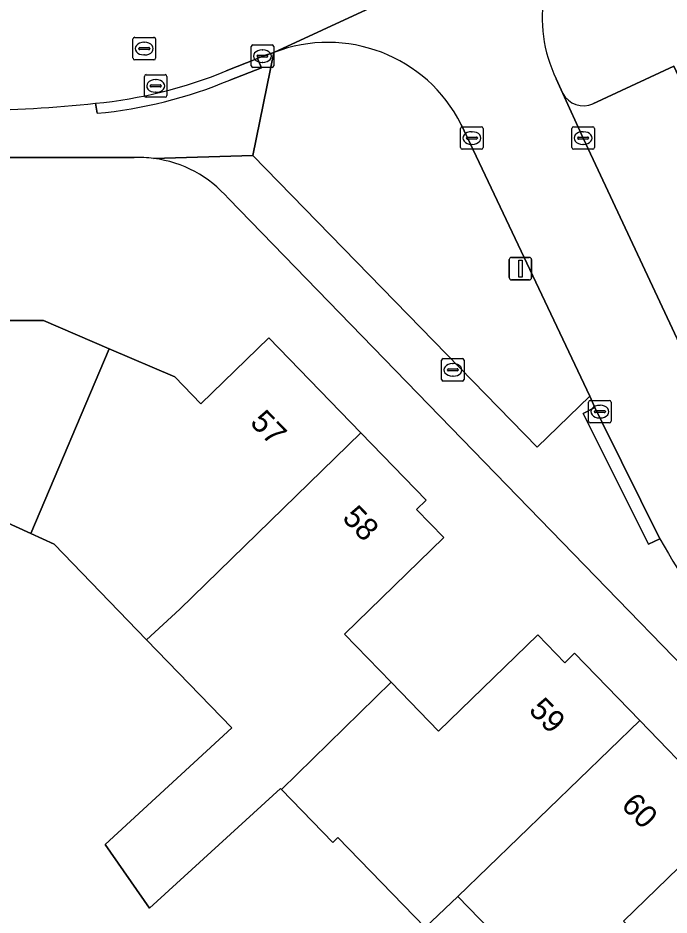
# Model space of a CAD drawing. Extents: x 162879 to 165540, y 384011 to 385181.
# Drawn here: x 163852.88 to 163881.82, y 384275.54 to 384315.4 of the extents above; entities that cross this region are included whole.
import ezdxf

# ---------------------------------------------------------------- set-up
doc = ezdxf.new("R2010")
doc.units = 0
for name, color, linetype in [('IMGEO_Erf', 7, 'Continuous'), ('IMGEO_Groenvoorziening', 7, 'Continuous'), ('IMGEO_Kolk', 7, 'Continuous'), ('IMGEO_Lichtmast', 7, 'Continuous'), ('IMGEO_Pand', 7, 'Continuous'), ('IMGEO_Pand_nummerreeks', 7, 'Continuous'), ('IMGEO_Parkeervlak_open', 7, 'Continuous'), ('IMGEO_Rijbaan_lokaal_gesloten', 7, 'Continuous'), ('IMGEO_Rioolput', 7, 'Continuous'), ('IMGEO_Voetpad_open', 7, 'Continuous')]:
    doc.layers.add(name, color=color, linetype=linetype)

msp = doc.modelspace()

# ---------------------------------------------------------------- linework, layer by layer
at = {"layer": 'IMGEO_Erf'}
for points in [[(163858.049, 384309.199), (163850.754, 384309.197)], [(163899.33, 384269.205), (163862.239, 384307.377)], [(163852.36, 384301.956), (163854.02, 384301.957), (163856.929, 384300.707), (163859.847, 384299.453), (163861.001, 384298.26), (163864.034, 384301.194), (163868.122, 384296.969), (163871.022, 384293.972), (163870.6, 384293.562), (163871.811, 384292.314), (163867.394, 384288.028), (163869.463, 384285.896), (163871.58, 384283.715), (163875.993, 384287.998), (163877.197, 384286.756), (163877.627, 384287.173), (163880.526, 384284.185), (163883.421, 384281.202), (163882.999, 384280.792), (163884.207, 384279.548), (163879.797, 384275.268)], [(163884.706, 384263.725), (163880.945, 384267.599), (163879.273, 384265.976), (163876.963, 384268.356), (163874.635, 384270.755), (163876.307, 384272.378), (163872.435, 384276.367), (163870.985, 384274.989), (163867.105, 384278.986), (163866.875, 384278.763), (163864.591, 384281.119), (163864.549, 384281.163), (163858.731, 384275.845), (163856.749, 384278.678), (163862.387, 384283.859), (163858.599, 384287.774), (163854.483, 384292.029), (163853.45, 384292.496), (163852.088, 384293.112)]]:
    msp.add_lwpolyline(points, dxfattribs=at)
for centre, radius, start, end in [((163858.24, 384303.908), 5.294, 82.74, 92.067), ((163858.245, 384303.919), 5.283, 40.8873, 82.7804)]:
    msp.add_arc(centre, radius, start, end, dxfattribs=at)
at = {"layer": 'IMGEO_Groenvoorziening'}
msp.add_lwpolyline([(163864.258, 384313.87), (163863.321, 384309.287), (163875.964, 384296.339), (163878.295, 384298.593), (163872.582, 384310.677)], dxfattribs=at)
msp.add_arc((163866.657, 384307.676), 6.642, 26.8577, 111.1697, dxfattribs=at)
at = {"layer": 'IMGEO_Kolk'}
for p, q in [((163863.321, 384314.206), (163864.173, 384314.206)), ((163863.246, 384313.28), (163863.246, 384314.132)), ((163863.734, 384313.986), (163863.759, 384313.986)), ((163864.247, 384314.132), (163864.247, 384313.28)), ((163863.505, 384313.7), (163863.505, 384313.712)), ((163863.943, 384313.663), (163863.545, 384313.663)), ((163863.548, 384313.749), (163863.946, 384313.749)), ((163863.757, 384313.426), (163863.732, 384313.426)), ((163863.989, 384313.712), (163863.989, 384313.7)), ((163864.173, 384313.206), (163863.321, 384313.206)), ((163872.558, 384309.641), (163872.558, 384310.493)), ((163872.633, 384310.567), (163873.485, 384310.567)), ((163873.046, 384310.347), (163873.071, 384310.347)), ((163873.559, 384310.493), (163873.559, 384309.641)), ((163877.502, 384309.641), (163877.502, 384310.493)), ((163877.577, 384310.567), (163878.429, 384310.567)), ((163877.99, 384310.347), (163878.015, 384310.347)), ((163878.503, 384310.493), (163878.503, 384309.641)), ((163872.817, 384310.061), (163872.817, 384310.073)), ((163873.255, 384310.024), (163872.857, 384310.024)), ((163872.86, 384310.11), (163873.258, 384310.11)), ((163873.301, 384310.073), (163873.301, 384310.061)), ((163877.761, 384310.061), (163877.761, 384310.073)), ((163878.199, 384310.024), (163877.801, 384310.024)), ((163877.804, 384310.11), (163878.202, 384310.11)), ((163878.245, 384310.073), (163878.245, 384310.061)), ((163873.485, 384309.567), (163872.633, 384309.567)), ((163873.069, 384309.787), (163873.044, 384309.787)), ((163878.429, 384309.567), (163877.577, 384309.567)), ((163878.013, 384309.787), (163877.988, 384309.787)), ((163871.786, 384300.267), (163872.638, 384300.267)), ((163871.711, 384299.341), (163871.711, 384300.193)), ((163872.199, 384300.047), (163872.224, 384300.047)), ((163872.712, 384300.193), (163872.712, 384299.341)), ((163871.97, 384299.761), (163871.97, 384299.773)), ((163872.408, 384299.724), (163872.01, 384299.724)), ((163872.013, 384299.81), (163872.411, 384299.81)), ((163872.222, 384299.487), (163872.197, 384299.487)), ((163872.454, 384299.773), (163872.454, 384299.761)), ((163872.638, 384299.267), (163871.786, 384299.267)), ((163878.248, 384297.486), (163878.248, 384298.338)), ((163878.323, 384298.412), (163879.175, 384298.412)), ((163879.249, 384298.338), (163879.249, 384297.486)), ((163878.507, 384297.906), (163878.507, 384297.918)), ((163878.945, 384297.869), (163878.547, 384297.869)), ((163878.55, 384297.955), (163878.948, 384297.955)), ((163878.736, 384298.192), (163878.761, 384298.192)), ((163878.991, 384297.918), (163878.991, 384297.906)), ((163878.759, 384297.632), (163878.734, 384297.632)), ((163879.175, 384297.412), (163878.323, 384297.412))]:
    msp.add_line(p, q, dxfattribs=at)
for points in [[(163863.321, 384314.206), (163864.173, 384314.206)], [(163863.246, 384313.28), (163863.246, 384314.132)], [(163864.247, 384314.132), (163864.247, 384313.28)], [(163864.173, 384313.206), (163863.321, 384313.206)], [(163872.558, 384309.641), (163872.558, 384310.493)], [(163872.633, 384310.567), (163873.485, 384310.567)], [(163873.559, 384310.493), (163873.559, 384309.641)], [(163877.502, 384309.641), (163877.502, 384310.493)], [(163877.577, 384310.567), (163878.429, 384310.567)], [(163878.503, 384310.493), (163878.503, 384309.641)], [(163873.485, 384309.567), (163872.633, 384309.567)], [(163878.429, 384309.567), (163877.577, 384309.567)], [(163871.786, 384300.267), (163872.638, 384300.267)], [(163871.711, 384299.341), (163871.711, 384300.193)], [(163872.712, 384300.193), (163872.712, 384299.341)], [(163872.638, 384299.267), (163871.786, 384299.267)], [(163878.248, 384297.486), (163878.248, 384298.338)], [(163878.323, 384298.412), (163879.175, 384298.412)], [(163879.249, 384298.338), (163879.249, 384297.486)], [(163879.175, 384297.412), (163878.323, 384297.412)]]:
    msp.add_lwpolyline(points, dxfattribs=at)
for centre, radius, start, end in [((163863.323, 384314.13), 0.0765, 91.552, 178.448), ((163863.323, 384314.13), 0.0765, 91.552, 178.448), ((163864.171, 384314.13), 0.0765, 1.552, 88.448), ((163864.171, 384314.13), 0.0765, 1.552, 88.448), ((163863.545, 384313.709), 0.0403, 85.8775, 175.7526), ((163863.542, 384313.699), 0.0366, 178.938, 274.7102), ((163863.946, 384313.706), 0.043, 264.8664, 352.4533), ((163863.95, 384313.711), 0.0386, 1.7309, 96.639), ((163863.323, 384313.282), 0.0765, 181.552, 268.448), ((163863.323, 384313.282), 0.0765, 181.552, 268.448), ((163864.171, 384313.282), 0.0765, 271.552, 358.448), ((163864.171, 384313.282), 0.0765, 271.552, 358.448), ((163872.635, 384310.491), 0.0765, 91.552, 178.448), ((163872.635, 384310.491), 0.0765, 91.552, 178.448), ((163873.483, 384310.491), 0.0765, 1.552, 88.448), ((163873.483, 384310.491), 0.0765, 1.552, 88.448), ((163877.579, 384310.491), 0.0765, 91.552, 178.448), ((163877.579, 384310.491), 0.0765, 91.552, 178.448), ((163878.427, 384310.491), 0.0765, 1.552, 88.448), ((163878.427, 384310.491), 0.0765, 1.552, 88.448), ((163872.857, 384310.07), 0.0403, 85.8775, 175.7526), ((163872.854, 384310.06), 0.0366, 178.938, 274.7102), ((163873.258, 384310.067), 0.043, 264.8664, 352.4533), ((163873.262, 384310.072), 0.0386, 1.7309, 96.639), ((163877.801, 384310.07), 0.0403, 85.8775, 175.7526), ((163877.798, 384310.06), 0.0366, 178.938, 274.7102), ((163878.202, 384310.067), 0.043, 264.8664, 352.4533), ((163878.206, 384310.072), 0.0386, 1.7309, 96.639), ((163872.635, 384309.643), 0.0765, 181.552, 268.448), ((163872.635, 384309.643), 0.0765, 181.552, 268.448), ((163873.483, 384309.643), 0.0765, 271.552, 358.448), ((163873.483, 384309.643), 0.0765, 271.552, 358.448), ((163877.579, 384309.643), 0.0765, 181.552, 268.448), ((163877.579, 384309.643), 0.0765, 181.552, 268.448), ((163878.427, 384309.643), 0.0765, 271.552, 358.448), ((163878.427, 384309.643), 0.0765, 271.552, 358.448), ((163871.788, 384300.191), 0.0765, 91.552, 178.448), ((163871.788, 384300.191), 0.0765, 91.552, 178.448), ((163872.636, 384300.191), 0.0765, 1.552, 88.448), ((163872.636, 384300.191), 0.0765, 1.552, 88.448), ((163872.01, 384299.77), 0.0403, 85.8775, 175.7526), ((163872.007, 384299.76), 0.0366, 178.938, 274.7102), ((163872.411, 384299.767), 0.043, 264.8664, 352.4533), ((163872.415, 384299.772), 0.0386, 1.7309, 96.639), ((163871.788, 384299.343), 0.0765, 181.552, 268.448), ((163871.788, 384299.343), 0.0765, 181.552, 268.448), ((163872.636, 384299.343), 0.0765, 271.552, 358.448), ((163872.636, 384299.343), 0.0765, 271.552, 358.448), ((163878.325, 384298.336), 0.0765, 91.552, 178.448), ((163878.325, 384298.336), 0.0765, 91.552, 178.448), ((163879.173, 384298.336), 0.0765, 1.552, 88.448), ((163879.173, 384298.336), 0.0765, 1.552, 88.448), ((163878.547, 384297.915), 0.0403, 85.8775, 175.7526), ((163878.544, 384297.905), 0.0366, 178.938, 274.7102), ((163878.948, 384297.912), 0.043, 264.8664, 352.4533), ((163878.952, 384297.917), 0.0386, 1.7309, 96.639), ((163878.325, 384297.488), 0.0765, 181.552, 268.448), ((163878.325, 384297.488), 0.0765, 181.552, 268.448), ((163879.173, 384297.488), 0.0765, 271.552, 358.448), ((163879.173, 384297.488), 0.0765, 271.552, 358.448)]:
    msp.add_arc(centre, radius, start, end, dxfattribs=at)
for centre, major_axis, ratio, start_param, end_param in [((163863.733, 384313.706), (-0.387, 0.002), 0.722429, 4.712389, 7.853982), ((163863.758, 384313.706), (-0.39, 0.002), 0.717154, 1.570796, 4.712389), ((163873.045, 384310.067), (-0.387, 0.002), 0.722429, 4.712389, 7.853982), ((163873.07, 384310.067), (-0.39, 0.002), 0.717154, 1.570796, 4.712389), ((163877.989, 384310.067), (-0.387, 0.002), 0.722429, 4.712389, 7.853982), ((163878.014, 384310.067), (-0.39, 0.002), 0.717154, 1.570796, 4.712389), ((163872.198, 384299.767), (-0.387, 0.002), 0.722429, 4.712389, 7.853982), ((163872.223, 384299.767), (-0.39, 0.002), 0.717154, 1.570796, 4.712389), ((163878.735, 384297.912), (-0.387, 0.002), 0.722429, 4.712389, 7.853982), ((163878.76, 384297.912), (-0.39, 0.002), 0.717154, 1.570796, 4.712389)]:
    msp.add_ellipse(centre, major_axis=major_axis, ratio=ratio, start_param=start_param, end_param=end_param, dxfattribs=at)
at = {"layer": 'IMGEO_Lichtmast'}
for p, q in [((163874.719, 384303.866), (163874.719, 384304.666)), ((163874.719, 384304.666), (163874.719, 384303.866)), ((163874.819, 384304.766), (163875.609, 384304.766)), ((163875.609, 384304.766), (163874.819, 384304.766)), ((163875.709, 384304.666), (163875.709, 384303.866)), ((163875.709, 384303.866), (163875.709, 384304.666)), ((163875.609, 384303.766), (163874.819, 384303.766)), ((163874.819, 384303.766), (163875.609, 384303.766))]:
    msp.add_line(p, q, dxfattribs=at)
msp.add_lwpolyline([(163875.139, 384304.641), (163875.289, 384304.641), (163875.289, 384303.891), (163875.139, 384303.891), (163875.139, 384304.641)], dxfattribs=at)
for centre, start, end in [((163874.819, 384304.666), 90, 180), ((163874.819, 384304.666), 90, 180), ((163875.609, 384304.666), 0, 90), ((163875.609, 384304.666), 360, 90), ((163874.819, 384303.866), 180, 270), ((163874.819, 384303.866), 180, 270), ((163875.609, 384303.866), 270, 0), ((163875.609, 384303.866), 270, 0)]:
    msp.add_arc(centre, 0.1, start, end, dxfattribs=at)
at = {"layer": 'IMGEO_Pand'}
for points in [[(163846.47, 384306.152), (163846.475, 384294.888), (163852.087, 384294.892), (163852.088, 384293.112), (163853.45, 384292.496), (163856.929, 384300.707), (163854.02, 384301.957), (163852.36, 384301.956), (163852.357, 384306.156)], [(163856.929, 384300.707), (163853.45, 384292.496), (163854.483, 384292.029), (163858.599, 384287.774), (163860.072, 384289.128), (163868.122, 384296.969), (163864.034, 384301.194), (163861.001, 384298.26), (163859.847, 384299.453)], [(163864.591, 384281.119), (163869.463, 384285.896), (163867.394, 384288.028), (163871.811, 384292.314), (163870.6, 384293.562), (163871.022, 384293.972), (163868.122, 384296.969), (163860.072, 384289.128), (163858.599, 384287.774), (163862.387, 384283.859), (163856.749, 384278.678), (163858.731, 384275.845), (163864.549, 384281.163)], [(163864.591, 384281.119), (163866.875, 384278.763), (163867.105, 384278.986), (163870.985, 384274.989), (163872.435, 384276.367), (163880.526, 384284.185), (163877.627, 384287.173), (163877.197, 384286.756), (163875.993, 384287.998), (163871.58, 384283.715), (163869.463, 384285.896)], [(163872.435, 384276.367), (163876.307, 384272.378), (163874.635, 384270.755), (163876.963, 384268.356), (163881.884, 384273.118), (163879.797, 384275.268), (163884.207, 384279.548), (163882.999, 384280.792), (163883.421, 384281.202), (163880.526, 384284.185)]]:
    msp.add_lwpolyline(points, close=True, dxfattribs=at)
at = {"layer": 'IMGEO_Parkeervlak_open'}
for points in [[(163884.802, 384298.021), (163888.388, 384299.683), (163882.043, 384313.266), (163878.44, 384311.595)], [(163877.096, 384312.046), (163878.002, 384310.066), (163882.733, 384299.973), (163884.265, 384296.82)]]:
    msp.add_lwpolyline(points, dxfattribs=at)
msp.add_arc((163878.016, 384312.561), 1.055, 209.2244, 293.6757, dxfattribs=at)
at = {"layer": 'IMGEO_Rijbaan_lokaal_gesloten'}
for points in [[(163862.135, 384313.051), (163863.528, 384313.607), (163863.746, 384313.708), (163864.258, 384313.87), (163879.48, 384320.926)], [(163879.48, 384320.926), (163864.258, 384313.87)], [(163884.46, 384296.42), (163884.395, 384296.553), (163884.331, 384296.686), (163884.265, 384296.82), (163882.733, 384299.973), (163878.002, 384310.066), (163877.096, 384312.046), (163876.805, 384312.696)], [(163872.582, 384310.677), (163878.295, 384298.593), (163878.531, 384298.094), (163878.861, 384297.396), (163881.414, 384292.267)]]:
    msp.add_lwpolyline(points, dxfattribs=at)
for centre, radius, start, end in [((163882.458, 384315.425), 6.277, 134.4361, 205.7719), ((163866.657, 384307.676), 6.642, 26.8577, 111.1697), ((163854.346, 384332.034), 20.519, 275.5367, 292.3082), ((163850.172, 384369.286), 58.002, 270.61824, 276.09038), ((163916.349, 384312.121), 40.183, 209.6097, 218.3807)]:
    msp.add_arc(centre, radius, start, end, dxfattribs=at)
at = {"layer": 'IMGEO_Rioolput'}
for p, q in [((163857.992, 384313.617), (163857.992, 384314.469)), ((163858.067, 384314.543), (163858.919, 384314.543)), ((163858.48, 384314.323), (163858.505, 384314.323)), ((163858.993, 384314.469), (163858.993, 384313.617)), ((163858.251, 384314.037), (163858.251, 384314.049)), ((163858.689, 384314), (163858.291, 384314)), ((163858.294, 384314.086), (163858.692, 384314.086)), ((163858.735, 384314.049), (163858.735, 384314.037)), ((163858.919, 384313.543), (163858.067, 384313.543)), ((163858.503, 384313.763), (163858.478, 384313.763)), ((163858.502, 384311.958), (163858.502, 384312.81)), ((163858.577, 384312.884), (163859.429, 384312.884)), ((163858.99, 384312.664), (163859.015, 384312.664)), ((163859.503, 384312.81), (163859.503, 384311.958)), ((163858.761, 384312.378), (163858.761, 384312.39)), ((163859.199, 384312.341), (163858.801, 384312.341)), ((163858.804, 384312.427), (163859.202, 384312.427)), ((163859.245, 384312.39), (163859.245, 384312.378)), ((163859.429, 384311.884), (163858.577, 384311.884)), ((163859.013, 384312.104), (163858.988, 384312.104))]:
    msp.add_line(p, q, dxfattribs=at)
for points in [[(163857.992, 384313.617), (163857.992, 384314.469)], [(163858.067, 384314.543), (163858.919, 384314.543)], [(163858.993, 384314.469), (163858.993, 384313.617)], [(163858.919, 384313.543), (163858.067, 384313.543)], [(163858.502, 384311.958), (163858.502, 384312.81)], [(163858.577, 384312.884), (163859.429, 384312.884)], [(163859.503, 384312.81), (163859.503, 384311.958)], [(163859.429, 384311.884), (163858.577, 384311.884)]]:
    msp.add_lwpolyline(points, dxfattribs=at)
for centre, radius, start, end in [((163858.069, 384314.467), 0.0765, 91.552, 178.448), ((163858.069, 384314.467), 0.0765, 91.552, 178.448), ((163858.917, 384314.467), 0.0765, 1.552, 88.448), ((163858.917, 384314.467), 0.0765, 1.552, 88.448), ((163858.291, 384314.046), 0.0403, 85.8775, 175.7526), ((163858.288, 384314.036), 0.0366, 178.938, 274.7102), ((163858.692, 384314.043), 0.043, 264.8664, 352.4533), ((163858.696, 384314.048), 0.0386, 1.7309, 96.639), ((163858.069, 384313.619), 0.0765, 181.552, 268.448), ((163858.069, 384313.619), 0.0765, 181.552, 268.448), ((163858.917, 384313.619), 0.0765, 271.552, 358.448), ((163858.917, 384313.619), 0.0765, 271.552, 358.448), ((163858.579, 384312.808), 0.0765, 91.552, 178.448), ((163858.579, 384312.808), 0.0765, 91.552, 178.448), ((163859.427, 384312.808), 0.0765, 1.552, 88.448), ((163859.427, 384312.808), 0.0765, 1.552, 88.448), ((163858.801, 384312.387), 0.0403, 85.8775, 175.7526), ((163858.798, 384312.377), 0.0366, 178.938, 274.7102), ((163859.202, 384312.384), 0.043, 264.8664, 352.4533), ((163859.206, 384312.389), 0.0386, 1.7309, 96.639), ((163858.579, 384311.96), 0.0765, 181.552, 268.448), ((163858.579, 384311.96), 0.0765, 181.552, 268.448), ((163859.427, 384311.96), 0.0765, 271.552, 358.448), ((163859.427, 384311.96), 0.0765, 271.552, 358.448)]:
    msp.add_arc(centre, radius, start, end, dxfattribs=at)
for centre, major_axis, ratio, start_param, end_param in [((163858.479, 384314.043), (-0.387, 0.002), 0.722429, 4.712389, 7.853982), ((163858.504, 384314.043), (-0.39, 0.002), 0.717154, 1.570796, 4.712389), ((163858.989, 384312.384), (-0.387, 0.002), 0.722429, 4.712389, 7.853982), ((163859.014, 384312.384), (-0.39, 0.002), 0.717154, 1.570796, 4.712389)]:
    msp.add_ellipse(centre, major_axis=major_axis, ratio=ratio, start_param=start_param, end_param=end_param, dxfattribs=at)
at = {"layer": 'IMGEO_Voetpad_open'}
for points in [[(163858.909, 384309.16), (163863.321, 384309.287), (163864.258, 384313.87)], [(163864.258, 384313.87), (163863.746, 384313.708), (163863.528, 384313.607), (163863.711, 384313.189), (163862.293, 384312.644)], [(163862.293, 384312.644), (163863.711, 384313.189), (163863.528, 384313.607), (163862.135, 384313.051)], [(163878.44, 384311.595), (163882.043, 384313.266), (163888.388, 384299.683), (163888.585, 384299.268), (163889.645, 384299.764), (163893.617, 384293.905), (163892.593, 384292.912), (163892.97, 384292.54), (163895.053, 384290.227), (163901.634, 384283.506), (163898.767, 384280.751)], [(163876.805, 384312.696), (163877.096, 384312.046)], [(163856.326, 384311.611), (163856.395, 384311.17)], [(163856.395, 384311.17), (163856.326, 384311.611)], [(163850.798, 384311.287), (163846.571, 384311.296), (163840.613, 384311.28), (163840.609, 384310.841), (163834.604, 384310.845), (163834.592, 384311.29), (163826.092, 384311.279), (163822.842, 384311.282), (163822.842, 384310.833), (163816.835, 384310.847), (163816.821, 384311.291), (163805.583, 384311.283), (163805.351, 384311.277), (163805.365, 384310.834), (163801.593, 384310.831), (163801.597, 384311.274), (163798.545, 384311.271), (163798.53, 384309.151), (163801.871, 384309.184), (163850.754, 384309.197), (163858.049, 384309.199)], [(163878.011, 384297.835), (163878.531, 384298.094), (163878.295, 384298.593), (163875.964, 384296.339), (163863.321, 384309.287), (163858.909, 384309.16)], [(163862.239, 384307.377), (163899.33, 384269.205)], [(163881.414, 384292.267), (163880.914, 384292.017), (163878.011, 384297.835)]]:
    msp.add_lwpolyline(points, dxfattribs=at)
msp.add_lwpolyline([(163878.861, 384297.396), (163878.531, 384298.094), (163878.011, 384297.835), (163880.914, 384292.017), (163881.414, 384292.267)], close=True, dxfattribs=at)
for centre, radius, start, end in [((163882.458, 384315.425), 6.277, 134.4361, 205.7719), ((163854.346, 384332.034), 20.519, 275.5367, 292.3082), ((163854.566, 384331.024), 19.938, 275.2622, 292.8011), ((163854.566, 384331.024), 19.938, 275.2622, 292.8011), ((163878.016, 384312.561), 1.055, 209.2244, 293.6757), ((163850.172, 384369.286), 58.002, 270.61824, 276.09038), ((163858.24, 384303.908), 5.294, 82.74, 92.067), ((163858.245, 384303.919), 5.283, 40.8873, 82.7804), ((163916.349, 384312.121), 40.183, 209.6097, 218.3807)]:
    msp.add_arc(centre, radius, start, end, dxfattribs=at)

# ---------------------------------------------------------------- texts
at = {"layer": 'IMGEO_Pand_nummerreeks'}
for s, rotation, p in [('57', 314.0566, (163863.151, 384297.389)), ('58', 314.0545, (163867.252, 384293.15)), ('59', 314.1381, (163875.545, 384284.61)), ('60', 314.1381, (163879.65, 384280.378))]:
    msp.add_text(s, height=1, rotation=rotation, dxfattribs=at).set_placement(p)

doc.saveas('drawing.dxf')
